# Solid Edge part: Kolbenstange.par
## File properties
Author: bmolnar
Last saved by: bmolnar
Revision: 77
Sűrűség: 0,000 kg/m^3
Pontosság: 0,990
Username: bmolnar
Dokumentum tartalom típus: 0
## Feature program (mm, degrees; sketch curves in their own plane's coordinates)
base feature "unnamed BaseFeature 1"
sketch for "unnamed Protrusion 1" plane through (0, 0, -16.4) normal (0, 0, -1) x-axis (0, 1, 0)
  circle centre (0, 0) radius 16
extrude "unnamed Protrusion 1" add finite 18.25 along +normal
sketch for "Kihúzás_2" #1 plane through (0, 0, -16.4) normal (0, 0, -1) x-axis (0, 1, 0)
  circle centre (0, 0) radius 6
sketch for "Kihúzás_2" #2 plane through (0, 0, -16.4) normal (0, 0, -1) x-axis (0, 1, 0)
  circle centre (0, 0) radius 16
extrude "Kihúzás_2" add finite 12.35 along -normal
sketch for "Furat_1" plane through (0, 0, 13.9) normal (0, 0, 1) x-axis (0, -1, 0)
  hole centre (0, 0) bore radius 2.4585
hole "Furat_1" nominal diameter 6 finite  VBottomAngle = 118 deg; ThreadDepth = 12.5 mm
chamfer "Letörés_1" setback 0.5  SetBackValue2 = 45 deg
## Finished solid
Body 1: solid body, 17 faces, 23 edges, 11 vertices.
  Faces by surface: plane 8, cylinder 5, cone 3, torus 1
  Edges by curve: circle 13, line 6, curve on surface 2, ellipse 2
Bounding box of the edges (mm; curved faces can reach further): 32.000 x 32.000 x 51.050, from (-16, -16, -34.65) to (16, 16, 16.4).
Cylindrical faces by radius (mm): R2.4585 x2, R3.125 x1, R6 x1, R16 x1
Conical faces (half-angle, radius in mm at the cone's reference point): 45 deg R2.9585 x1, 45 deg R3.225 x1, 59 deg R2.4585 x1
Toroidal faces (ring radius, tube radius in mm): R4.7 r1.3 x1
Planar faces by outward normal: +x 1, +z 3, -x 1, -z 1, oblique 2
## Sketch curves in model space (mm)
circle centre (0, 0, -16.4) radius 16
circle centre (0, 0, -16.4) radius 6
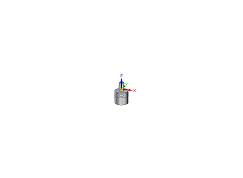
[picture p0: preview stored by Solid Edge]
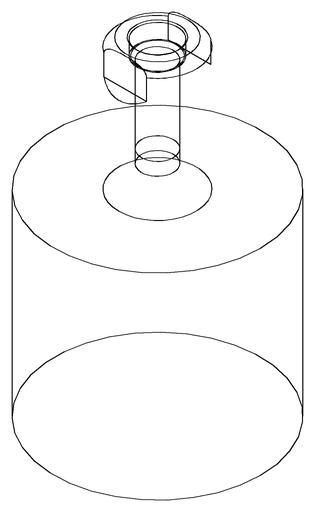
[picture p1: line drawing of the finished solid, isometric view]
